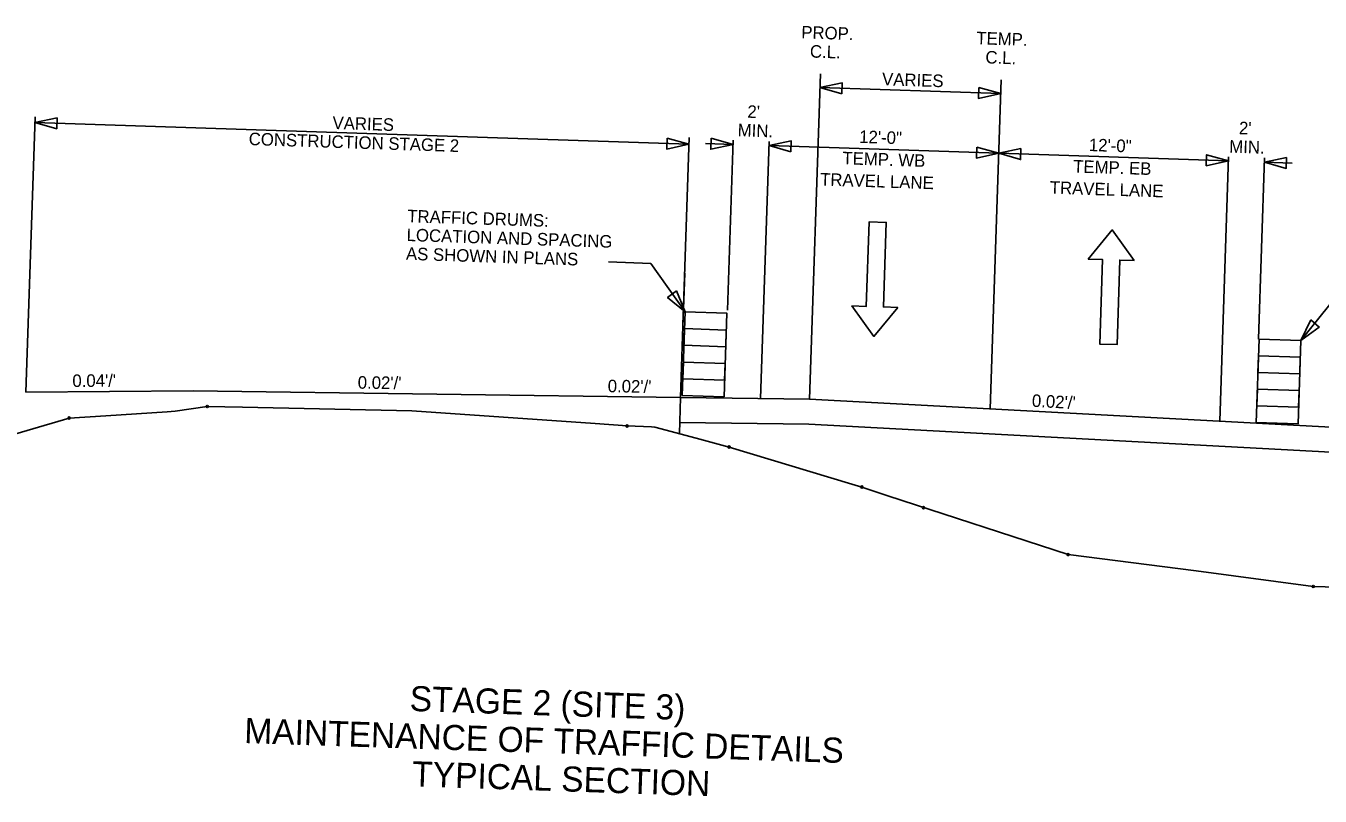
# Model space of a CAD drawing. Extents: x 977258 to 978774, y 1525947 to 1526932.
# Drawn here: x 977645 to 978264, y 1526544 to 1526912 of the extents above; entities that cross this region are included whole.
import ezdxf

# ---------------------------------------------------------------- set-up
doc = ezdxf.new("R2010")
doc.units = 0
for name, color, linetype in [('B_border', 7, 'Continuous'), ('B_County and Route', 7, 'Continuous'), ('B_Preliminary', 7, 'Continuous'), ('B_Print_Date_Text', 7, 'Continuous'), ('B_Title Text', 7, 'Continuous'), ('Default', 7, 'Continuous'), ('R_Border', 7, 'Continuous'), ('R_MOT', 7, 'Continuous'), ('STAMP_PP', 7, 'Continuous')]:
    doc.layers.add(name, color=color, linetype=linetype)

msp = doc.modelspace()

# ---------------------------------------------------------------- linework, layer by layer
at = {"layer": 'B_border'}
for centre in [(977731.73, 1526730.1), (977665.58, 1526724.58), (977932.64, 1526720.78), (977981.46, 1526710.71), (978045.03, 1526691.56), (978074.48, 1526681.68), (978143.72, 1526659.23), (978261.1, 1526644)]:
    msp.add_circle(centre, 0.5, dxfattribs=at)
at = {"layer": 'B_County and Route'}
for p, q in [((978019.99, 1526733.59), (978025.19, 1526889.28)), ((978106.44, 1526728.97), (978111.69, 1526886.4))]:
    msp.add_line(p, q, dxfattribs=at)
at = {"layer": 'B_Preliminary'}
msp.add_lwpolyline([(977590.5, 1526702.57), (977665.58, 1526724.58), (977683.24, 1526725.62), (977712.46, 1526727.47), (977716.28, 1526727.8), (977731.73, 1526730.1), (977748.57, 1526729.75), (977829.7, 1526727.99), (977917.45, 1526721.89), (977932.64, 1526720.78), (977944.35, 1526720.32), (977945.99, 1526720.26), (977965.72, 1526714.93), (977981.46, 1526710.71), (978040.15, 1526692.86), (978045.03, 1526691.56), (978057.39, 1526687.35), (978143.72, 1526659.23), (978205.08, 1526651.49), (978261.1, 1526644), (978358.12, 1526641.28)], dxfattribs=at)
at = {"layer": 'B_Print_Date_Text'}
for p, q in [((977644.9, 1526736.99), (977724.96, 1526737.52)), ((977724.96, 1526737.52), (977958.24, 1526734.41)), ((977957.66, 1526717.11), (977958.24, 1526734.41)), ((977958.24, 1526734.41), (978019.99, 1526733.59)), ((978314.63, 1526717.86), (978019.99, 1526733.59)), ((977957.84, 1526722.48), (978019.6, 1526721.66)), ((978464.53, 1526697.9), (978019.6, 1526721.66))]:
    msp.add_line(p, q, dxfattribs=at)
at = {"layer": 'B_Title Text'}
for p, q in [((977959.22, 1526763.88), (977960.22, 1526793.85)), ((977960.22, 1526793.85), (977959.41, 1526769.48))]:
    msp.add_line(p, q, dxfattribs=at)
at = {"layer": 'Default'}
for points in [[(978062.22, 1526777.51), (978050.75, 1526763.6), (978040.23, 1526778.24), (978047.1, 1526778.01), (978048.45, 1526818.45), (978056.7, 1526818.17), (978055.35, 1526777.74)], [(978175.36, 1526799.93), (978164.84, 1526814.57), (978153.37, 1526800.66), (978160.24, 1526800.43), (978158.89, 1526760), (978167.14, 1526759.72), (978168.48, 1526800.16)]]:
    msp.add_lwpolyline(points, close=True, dxfattribs=at)
at = {"layer": 'R_MOT'}
for points in [[(977979.06, 1526734.71), (977959.07, 1526735.38), (977960.41, 1526775.36), (977980.4, 1526774.69)], [(977980.13, 1526766.69), (977960.14, 1526767.36), (977959.87, 1526759.37), (977979.86, 1526758.7)], [(978233.79, 1526722.41), (978253.78, 1526721.74), (978255.12, 1526761.72), (978235.13, 1526762.38)], [(978234.86, 1526754.39), (978254.85, 1526753.72), (978254.58, 1526745.73), (978234.59, 1526746.39)], [(977979.6, 1526750.7), (977959.61, 1526751.37), (977959.34, 1526743.37), (977979.33, 1526742.71)], [(978234.33, 1526738.4), (978254.32, 1526737.73), (978254.05, 1526729.74), (978234.06, 1526730.4)]]:
    msp.add_lwpolyline(points, close=True, dxfattribs=at)
at = {"layer": 'STAMP_PP'}
for p, q in [((978024.97, 1526882.68), (978111.47, 1526879.8)), ((977644.9, 1526736.99), (977649.29, 1526868.65)), ((977962.28, 1526855.57), (977649.2, 1526866.01)), ((977980.73, 1526776.24), (977983.44, 1526857.51)), ((977983.37, 1526855.48), (977970.14, 1526855.92)), ((977996.55, 1526733.9), (978000.65, 1526856.93)), ((978000.58, 1526854.91), (978110.52, 1526851.24)), ((978220.46, 1526847.57), (978110.52, 1526851.24)), ((978216.31, 1526723.11), (978220.53, 1526849.6)), ((978234.85, 1526762.39), (978237.74, 1526849.03)), ((978237.67, 1526847), (978250.9, 1526846.56)), ((977923.72, 1526799.25), (977944.08, 1526798.57)), ((977944.08, 1526798.57), (977960.41, 1526775.36)), ((978272.95, 1526783.79), (978255.12, 1526761.72))]:
    msp.add_line(p, q, dxfattribs=at)
for points in [[(978035.43, 1526879.69), (978024.97, 1526882.68), (978035.61, 1526884.97)], [(978101.01, 1526882.79), (978111.47, 1526879.8), (978100.83, 1526877.51)], [(977659.84, 1526868.3), (977649.2, 1526866.01), (977659.67, 1526863.02)], [(977951.81, 1526858.56), (977962.28, 1526855.57), (977951.64, 1526853.29)], [(977972.91, 1526858.47), (977983.37, 1526855.48), (977972.73, 1526853.19)], [(978011.05, 1526851.92), (978000.58, 1526854.91), (978011.22, 1526857.19)], [(978100.05, 1526854.23), (978110.52, 1526851.24), (978099.88, 1526848.95)], [(978121.16, 1526853.53), (978110.52, 1526851.24), (978120.99, 1526848.25)], [(978209.82, 1526845.29), (978220.46, 1526847.57), (978209.99, 1526850.57)], [(978248.31, 1526849.29), (978237.67, 1526847), (978248.13, 1526844.01)], [(977956.31, 1526785.44), (977960.41, 1526775.36), (977952.04, 1526782.32)], [(978259.88, 1526771.51), (978255.12, 1526761.72), (978263.93, 1526768.11)]]:
    msp.add_lwpolyline(points, close=True, dxfattribs=at)
msp.add_lwpolyline([(977958.24, 1526734.41), (977959.21, 1526763.69), (977962.39, 1526858.82)], dxfattribs=at)

# ---------------------------------------------------------------- texts
at = {"layer": 'R_Border'}
for s, height, rotation, p in [('PROP.', 6, 358.09005, (978015.95, 1526906.24)), ('TEMP.', 6, 358.09005, (978099.71, 1526903.45)), ('C.L.', 6, 358.09005, (978020.09, 1526897.1)), ('C.L.', 6, 358.09005, (978104.08, 1526894.3)), ('VARIES', 6, 358.09005, (978054.61, 1526883.84)), ("2'", 6, 358.09005, (977990.15, 1526868.28)), ('VARIES', 6, 358.09005, (977791.58, 1526862.89)), ('MIN.', 6, 358.09005, (977985.51, 1526859.43)), ("2'", 6, 358.09005, (978225.43, 1526860.43)), ('CONSTRUCTION STAGE 2', 6, 358.09005, (977751.48, 1526855.22)), ('12\'-0"', 6, 358.09005, (978043.67, 1526856.26)), ('12\'-0"', 6, 358.09005, (978153.6, 1526852.35)), ('MIN.', 6, 358.09005, (978220.78, 1526851.58)), ('TEMP. WB', 6, 358.09005, (978035.63, 1526846.02)), ('TEMP. EB', 6, 358.09005, (978146.08, 1526842.09)), ('TRAVEL LANE', 6, 358.09005, (978024.96, 1526835.87)), ('TRAVEL LANE', 6, 358.09005, (978134.89, 1526831.96)), ('TRAFFIC DRUMS:', 6, 358.09005, (977827.35, 1526818.29)), ('LOCATION AND SPACING ', 6, 358.09005, (977827.05, 1526809.3)), ('AS SHOWN IN PLANS', 6, 358.09005, (977826.75, 1526800.3)), ("0.04'/'", 6, 0.38066, (977667.17, 1526739.43)), ("0.02'/'", 6, 359.23582, (977803.7, 1526738.65)), ("0.02'/'", 6, 359.23582, (977923.35, 1526736.92)), ("0.02'/'", 6, 356.94429, (978126.28, 1526729.99)), ('STAGE 2 (SITE 3)', 12, 358.09005, (977828.46, 1526584.44)), ('MAINTENANCE OF TRAFFIC DETAILS', 12, 358.09005, (977749.29, 1526569.07)), ('TYPICAL SECTION ', 12, 358.09005, (977829.66, 1526548.38))]:
    msp.add_text(s, height=height, rotation=rotation, dxfattribs=at).set_placement(p)

doc.saveas('drawing.dxf')
